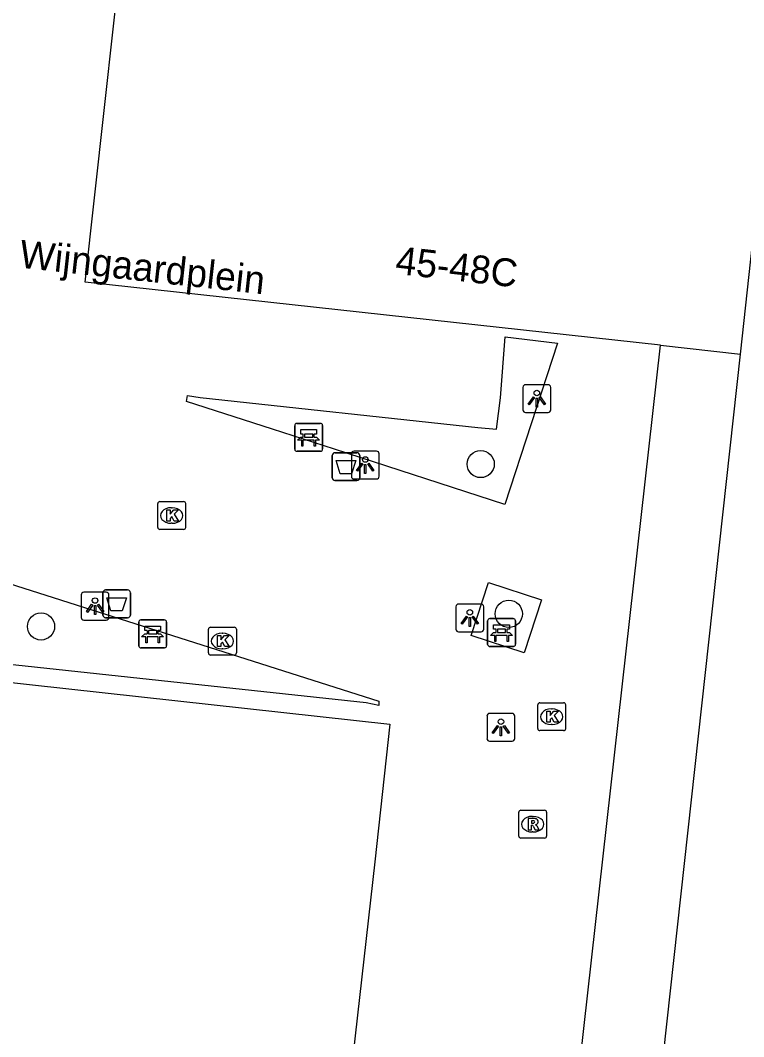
# Model space of a CAD drawing. Extents: x 162026 to 163499, y 387297 to 388169.
# Drawn here: x 162360.5 to 162386.47, y 387569.33 to 387605.84 of the extents above; entities that cross this region are included whole.
import ezdxf

# ---------------------------------------------------------------- set-up
doc = ezdxf.new("R2010")
doc.units = 0
for name, color, linetype in [('IMGEO_Afvalbak', 7, 'Continuous'), ('IMGEO_Bank', 7, 'Continuous'), ('IMGEO_Boom', 7, 'Continuous'), ('IMGEO_Kolk', 7, 'Continuous'), ('IMGEO_Lichtpunt', 7, 'Continuous'), ('IMGEO_Openbare_ruimte_label', 7, 'Continuous'), ('IMGEO_Pand', 7, 'Continuous'), ('IMGEO_Pand_nummerreeks', 7, 'Continuous'), ('IMGEO_Rioolput', 7, 'Continuous'), ('IMGEO_Voetpad_open', 7, 'Continuous')]:
    doc.layers.add(name, color=color, linetype=linetype)

msp = doc.modelspace()

# ---------------------------------------------------------------- linework, layer by layer
at = {"layer": 'IMGEO_Afvalbak'}
for p, q in [((162371.695, 387589.41), (162371.695, 387590.21)), ((162371.695, 387590.21), (162371.695, 387589.41)), ((162371.795, 387590.31), (162372.585, 387590.31)), ((162372.585, 387590.31), (162371.795, 387590.31)), ((162372.685, 387590.21), (162372.685, 387589.41)), ((162372.685, 387589.41), (162372.685, 387590.21)), ((162372.585, 387589.31), (162371.795, 387589.31)), ((162371.795, 387589.31), (162372.585, 387589.31)), ((162363.461, 387584.479), (162363.461, 387585.279)), ((162363.461, 387585.279), (162363.461, 387584.479)), ((162363.561, 387585.379), (162364.351, 387585.379)), ((162364.351, 387585.379), (162363.561, 387585.379)), ((162364.451, 387585.279), (162364.451, 387584.479)), ((162364.451, 387584.479), (162364.451, 387585.279)), ((162364.351, 387584.379), (162363.561, 387584.379)), ((162363.561, 387584.379), (162364.351, 387584.379))]:
    msp.add_line(p, q, dxfattribs=at)
for points in [[(162371.838, 387590.024), (162372.542, 387590.024), (162372.393, 387589.554), (162371.987, 387589.554), (162371.838, 387590.024)], [(162363.604, 387585.093), (162364.308, 387585.093), (162364.159, 387584.623), (162363.753, 387584.623), (162363.604, 387585.093)]]:
    msp.add_lwpolyline(points, dxfattribs=at)
for centre, start, end in [((162371.795, 387590.21), 90, 180), ((162371.795, 387590.21), 90, 180), ((162372.585, 387590.21), 0, 90), ((162372.585, 387590.21), 360, 90), ((162371.795, 387589.41), 180, 270), ((162371.795, 387589.41), 180, 270), ((162372.585, 387589.41), 270, 0), ((162372.585, 387589.41), 270, 0), ((162363.561, 387585.279), 90, 180), ((162363.561, 387585.279), 90, 180), ((162364.351, 387585.279), 0, 90), ((162364.351, 387585.279), 360, 90), ((162363.561, 387584.479), 180, 270), ((162363.561, 387584.479), 180, 270), ((162364.351, 387584.479), 270, 0), ((162364.351, 387584.479), 270, 0)]:
    msp.add_arc(centre, 0.1, start, end, dxfattribs=at)
at = {"layer": 'IMGEO_Bank'}
for p, q in [((162370.349, 387590.437), (162370.349, 387591.278)), ((162370.349, 387591.278), (162370.349, 387590.437)), ((162370.424, 387591.362), (162371.265, 387591.362)), ((162371.265, 387591.362), (162370.424, 387591.362)), ((162371.349, 387591.287), (162371.349, 387590.446)), ((162371.349, 387590.446), (162371.349, 387591.287)), ((162370.658, 387590.868), (162370.658, 387590.974)), ((162370.702, 387590.974), (162370.702, 387590.868)), ((162370.99, 387590.98), (162370.708, 387590.98)), ((162370.996, 387590.868), (162370.996, 387590.974)), ((162371.04, 387590.974), (162371.04, 387590.868)), ((162371.046, 387590.76), (162370.653, 387590.76)), ((162370.708, 387590.862), (162370.99, 387590.862)), ((162371.274, 387590.362), (162370.433, 387590.362)), ((162370.433, 387590.362), (162371.274, 387590.362)), ((162377.35, 387584.348), (162378.191, 387584.348)), ((162378.191, 387584.348), (162377.35, 387584.348)), ((162364.749, 387583.375), (162364.749, 387584.216)), ((162364.749, 387584.216), (162364.749, 387583.375)), ((162364.824, 387584.3), (162365.665, 387584.3)), ((162365.665, 387584.3), (162364.824, 387584.3)), ((162365.749, 387584.225), (162365.749, 387583.384)), ((162365.749, 387583.384), (162365.749, 387584.225)), ((162377.275, 387583.423), (162377.275, 387584.264)), ((162377.275, 387584.264), (162377.275, 387583.423)), ((162378.275, 387584.273), (162378.275, 387583.432)), ((162378.275, 387583.432), (162378.275, 387584.273)), ((162365.446, 387583.698), (162365.053, 387583.698)), ((162365.058, 387583.806), (162365.058, 387583.912)), ((162365.102, 387583.912), (162365.102, 387583.806)), ((162365.39, 387583.918), (162365.108, 387583.918)), ((162365.108, 387583.8), (162365.39, 387583.8)), ((162365.396, 387583.806), (162365.396, 387583.912)), ((162365.44, 387583.912), (162365.44, 387583.806)), ((162377.972, 387583.746), (162377.579, 387583.746)), ((162377.584, 387583.854), (162377.584, 387583.96)), ((162377.628, 387583.96), (162377.628, 387583.854)), ((162377.916, 387583.966), (162377.634, 387583.966)), ((162377.634, 387583.848), (162377.916, 387583.848)), ((162377.922, 387583.854), (162377.922, 387583.96)), ((162377.966, 387583.96), (162377.966, 387583.854)), ((162365.674, 387583.3), (162364.833, 387583.3)), ((162364.833, 387583.3), (162365.674, 387583.3)), ((162378.2, 387583.348), (162377.359, 387583.348)), ((162377.359, 387583.348), (162378.2, 387583.348))]:
    msp.add_line(p, q, dxfattribs=at)
for points in [[(162370.652, 387590.98), (162370.566, 387590.98), (162370.566, 387591.141), (162371.129, 387591.141), (162371.129, 387590.98), (162371.046, 387590.98)], [(162370.596, 387590.76), (162370.454, 387590.76), (162370.566, 387590.862), (162370.652, 387590.862)], [(162370.646, 387590.753), (162370.646, 387590.546), (162370.603, 387590.546), (162370.603, 387590.753)], [(162371.046, 387590.862), (162371.129, 387590.862), (162371.241, 387590.76), (162371.102, 387590.76)], [(162371.096, 387590.753), (162371.096, 387590.546), (162371.052, 387590.546), (162371.052, 387590.753)], [(162365.052, 387583.918), (162364.966, 387583.918), (162364.966, 387584.079), (162365.529, 387584.079), (162365.529, 387583.918), (162365.446, 387583.918)], [(162377.578, 387583.966), (162377.492, 387583.966), (162377.492, 387584.127), (162378.055, 387584.127), (162378.055, 387583.966), (162377.972, 387583.966)], [(162364.996, 387583.698), (162364.854, 387583.698), (162364.966, 387583.8), (162365.052, 387583.8)], [(162365.046, 387583.691), (162365.046, 387583.484), (162365.003, 387583.484), (162365.003, 387583.691)], [(162365.446, 387583.8), (162365.529, 387583.8), (162365.641, 387583.698), (162365.502, 387583.698)], [(162365.496, 387583.691), (162365.496, 387583.484), (162365.452, 387583.484), (162365.452, 387583.691)], [(162377.522, 387583.746), (162377.38, 387583.746), (162377.492, 387583.848), (162377.578, 387583.848)], [(162377.572, 387583.739), (162377.572, 387583.532), (162377.529, 387583.532), (162377.529, 387583.739)], [(162377.972, 387583.848), (162378.055, 387583.848), (162378.167, 387583.746), (162378.028, 387583.746)], [(162378.022, 387583.739), (162378.022, 387583.532), (162377.978, 387583.532), (162377.978, 387583.739)]]:
    msp.add_lwpolyline(points, dxfattribs=at)
for centre, radius, start, end in [((162370.427, 387591.284), 0.0779, 92.4484, 184.2845), ((162370.427, 387591.284), 0.0779, 92.4484, 184.2845), ((162371.271, 387591.284), 0.0779, 2.4484, 94.2845), ((162371.271, 387591.284), 0.0779, 2.4484, 94.2845), ((162370.651, 387590.973), 0.00671, 2.8957, 87.1043), ((162370.708, 387590.973), 0.00671, 92.8957, 177.1043), ((162370.99, 387590.973), 0.00671, 2.8957, 87.1043), ((162371.047, 387590.973), 0.00671, 92.8957, 177.1043), ((162370.596, 387590.753), 0.00671, 2.8957, 87.1043), ((162370.653, 387590.753), 0.00671, 92.8957, 177.1043), ((162370.651, 387590.869), 0.00671, 272.8957, 357.1043), ((162370.708, 387590.869), 0.00671, 182.8957, 267.1043), ((162370.99, 387590.869), 0.00671, 272.8957, 357.1043), ((162371.047, 387590.869), 0.00671, 182.8957, 267.1043), ((162371.045, 387590.753), 0.00671, 2.8957, 87.1043), ((162371.102, 387590.753), 0.00671, 92.8957, 177.1043), ((162370.427, 387590.44), 0.0779, 182.4484, 274.2845), ((162370.427, 387590.44), 0.0779, 182.4484, 274.2845), ((162371.271, 387590.44), 0.0779, 272.4484, 4.2845), ((162371.271, 387590.44), 0.0779, 272.4484, 4.2845), ((162377.353, 387584.27), 0.0779, 92.4484, 184.2845), ((162377.353, 387584.27), 0.0779, 92.4484, 184.2845), ((162378.197, 387584.27), 0.0779, 2.4484, 94.2845), ((162378.197, 387584.27), 0.0779, 2.4484, 94.2845), ((162364.827, 387584.222), 0.0779, 92.4484, 184.2845), ((162364.827, 387584.222), 0.0779, 92.4484, 184.2845), ((162365.671, 387584.222), 0.0779, 2.4484, 94.2845), ((162365.671, 387584.222), 0.0779, 2.4484, 94.2845), ((162364.996, 387583.691), 0.00671, 2.8957, 87.1043), ((162365.053, 387583.691), 0.00671, 92.8957, 177.1043), ((162365.051, 387583.911), 0.00671, 2.8957, 87.1043), ((162365.051, 387583.807), 0.00671, 272.8957, 357.1043), ((162365.108, 387583.911), 0.00671, 92.8957, 177.1043), ((162365.108, 387583.807), 0.00671, 182.8957, 267.1043), ((162365.39, 387583.911), 0.00671, 2.8957, 87.1043), ((162365.39, 387583.807), 0.00671, 272.8957, 357.1043), ((162365.447, 387583.911), 0.00671, 92.8957, 177.1043), ((162365.447, 387583.807), 0.00671, 182.8957, 267.1043), ((162365.445, 387583.691), 0.00671, 2.8957, 87.1043), ((162365.502, 387583.691), 0.00671, 92.8957, 177.1043), ((162377.522, 387583.739), 0.00671, 2.8957, 87.1043), ((162377.579, 387583.739), 0.00671, 92.8957, 177.1043), ((162377.577, 387583.959), 0.00671, 2.8957, 87.1043), ((162377.577, 387583.855), 0.00671, 272.8957, 357.1043), ((162377.634, 387583.959), 0.00671, 92.8957, 177.1043), ((162377.634, 387583.855), 0.00671, 182.8957, 267.1043), ((162377.916, 387583.959), 0.00671, 2.8957, 87.1043), ((162377.916, 387583.855), 0.00671, 272.8957, 357.1043), ((162377.973, 387583.959), 0.00671, 92.8957, 177.1043), ((162377.973, 387583.855), 0.00671, 182.8957, 267.1043), ((162377.971, 387583.739), 0.00671, 2.8957, 87.1043), ((162378.028, 387583.739), 0.00671, 92.8957, 177.1043), ((162364.827, 387583.378), 0.0779, 182.4484, 274.2845), ((162364.827, 387583.378), 0.0779, 182.4484, 274.2845), ((162365.671, 387583.378), 0.0779, 272.4484, 4.2845), ((162365.671, 387583.378), 0.0779, 272.4484, 4.2845), ((162377.353, 387583.426), 0.0779, 182.4484, 274.2845), ((162377.353, 387583.426), 0.0779, 182.4484, 274.2845), ((162378.197, 387583.426), 0.0779, 272.4484, 4.2845), ((162378.197, 387583.426), 0.0779, 272.4484, 4.2845)]:
    msp.add_arc(centre, radius, start, end, dxfattribs=at)
at = {"layer": 'IMGEO_Boom'}
for centre in [(162377.026, 387589.902), (162378.034, 387584.52), (162361.241, 387584.068)]:
    msp.add_circle(centre, 0.489, dxfattribs=at)
at = {"layer": 'IMGEO_Kolk'}
for p, q in [((162365.433, 387587.627), (162365.433, 387588.479)), ((162365.508, 387588.553), (162366.36, 387588.553)), ((162366.434, 387588.479), (162366.434, 387587.627)), ((162365.921, 387588.333), (162365.946, 387588.333)), ((162365.944, 387587.773), (162365.919, 387587.773)), ((162366.36, 387587.553), (162365.508, 387587.553)), ((162367.328, 387584.042), (162368.18, 387584.042)), ((162367.253, 387583.116), (162367.253, 387583.968)), ((162367.741, 387583.822), (162367.766, 387583.822)), ((162368.254, 387583.968), (162368.254, 387583.116)), ((162367.764, 387583.262), (162367.739, 387583.262)), ((162368.18, 387583.042), (162367.328, 387583.042)), ((162379.076, 387580.399), (162379.076, 387581.251)), ((162379.151, 387581.325), (162380.003, 387581.325)), ((162379.564, 387581.105), (162379.589, 387581.105)), ((162380.077, 387581.251), (162380.077, 387580.399)), ((162380.003, 387580.325), (162379.151, 387580.325)), ((162379.587, 387580.545), (162379.562, 387580.545))]:
    msp.add_line(p, q, dxfattribs=at)
for points in [[(162365.433, 387587.627), (162365.433, 387588.479)], [(162365.508, 387588.553), (162366.36, 387588.553)], [(162366.434, 387588.479), (162366.434, 387587.627)], [(162365.754, 387588.253), (162365.877, 387588.253), (162365.877, 387588.102), (162366.007, 387588.253), (162366.171, 387588.253), (162366.025, 387588.102), (162366.178, 387587.853), (162366.026, 387587.853), (162365.941, 387588.017), (162365.877, 387587.95), (162365.877, 387587.853), (162365.754, 387587.853), (162365.754, 387588.253)], [(162366.36, 387587.553), (162365.508, 387587.553)], [(162367.328, 387584.042), (162368.18, 387584.042)], [(162367.253, 387583.116), (162367.253, 387583.968)], [(162367.574, 387583.742), (162367.697, 387583.742), (162367.697, 387583.591), (162367.827, 387583.742), (162367.991, 387583.742), (162367.845, 387583.591), (162367.998, 387583.342), (162367.846, 387583.342), (162367.761, 387583.506), (162367.697, 387583.439), (162367.697, 387583.342), (162367.574, 387583.342), (162367.574, 387583.742)], [(162368.254, 387583.968), (162368.254, 387583.116)], [(162368.18, 387583.042), (162367.328, 387583.042)], [(162379.076, 387580.399), (162379.076, 387581.251)], [(162379.151, 387581.325), (162380.003, 387581.325)], [(162380.077, 387581.251), (162380.077, 387580.399)], [(162379.397, 387581.025), (162379.52, 387581.025), (162379.52, 387580.874), (162379.65, 387581.025), (162379.814, 387581.025), (162379.668, 387580.874), (162379.821, 387580.625), (162379.669, 387580.625), (162379.584, 387580.789), (162379.52, 387580.722), (162379.52, 387580.625), (162379.397, 387580.625), (162379.397, 387581.025)], [(162380.003, 387580.325), (162379.151, 387580.325)]]:
    msp.add_lwpolyline(points, dxfattribs=at)
for centre, start, end in [((162365.51, 387588.477), 91.552, 178.448), ((162365.51, 387588.477), 91.552, 178.448), ((162366.358, 387588.477), 1.552, 88.448), ((162366.358, 387588.477), 1.552, 88.448), ((162365.51, 387587.629), 181.552, 268.448), ((162365.51, 387587.629), 181.552, 268.448), ((162366.358, 387587.629), 271.552, 358.448), ((162366.358, 387587.629), 271.552, 358.448), ((162367.33, 387583.966), 91.552, 178.448), ((162367.33, 387583.966), 91.552, 178.448), ((162368.178, 387583.966), 1.552, 88.448), ((162368.178, 387583.966), 1.552, 88.448), ((162367.33, 387583.118), 181.552, 268.448), ((162367.33, 387583.118), 181.552, 268.448), ((162368.178, 387583.118), 271.552, 358.448), ((162368.178, 387583.118), 271.552, 358.448), ((162379.153, 387581.249), 91.552, 178.448), ((162379.153, 387581.249), 91.552, 178.448), ((162380.001, 387581.249), 1.552, 88.448), ((162380.001, 387581.249), 1.552, 88.448), ((162379.153, 387580.401), 181.552, 268.448), ((162379.153, 387580.401), 181.552, 268.448), ((162380.001, 387580.401), 271.552, 358.448), ((162380.001, 387580.401), 271.552, 358.448)]:
    msp.add_arc(centre, 0.0765, start, end, dxfattribs=at)
for centre, major_axis, ratio, start_param, end_param in [((162365.92, 387588.053), (-0.387, 0.002), 0.722429, 4.712389, 7.853982), ((162365.945, 387588.053), (-0.39, 0.002), 0.717154, 1.570796, 4.712389), ((162367.74, 387583.542), (-0.387, 0.002), 0.722429, 4.712389, 7.853982), ((162367.765, 387583.542), (-0.39, 0.002), 0.717154, 1.570796, 4.712389), ((162379.563, 387580.825), (-0.387, 0.002), 0.722429, 4.712389, 7.853982), ((162379.588, 387580.825), (-0.39, 0.002), 0.717154, 1.570796, 4.712389)]:
    msp.add_ellipse(centre, major_axis=major_axis, ratio=ratio, start_param=start_param, end_param=end_param, dxfattribs=at)
at = {"layer": 'IMGEO_Lichtpunt'}
for p, q in [((162379.446, 387592.752), (162378.638, 387592.752)), ((162379.446, 387592.752), (162378.638, 387592.752)), ((162378.544, 387592.657), (162378.544, 387591.85)), ((162378.544, 387592.657), (162378.544, 387591.85)), ((162379.54, 387591.85), (162379.54, 387592.657)), ((162379.54, 387591.85), (162379.54, 387592.657)), ((162378.638, 387591.756), (162379.446, 387591.756)), ((162378.638, 387591.756), (162379.446, 387591.756)), ((162372.384, 387590.268), (162372.384, 387589.461)), ((162372.384, 387590.268), (162372.384, 387589.461)), ((162373.286, 387590.363), (162372.478, 387590.363)), ((162373.286, 387590.363), (162372.478, 387590.363)), ((162373.38, 387589.461), (162373.38, 387590.268)), ((162373.38, 387589.461), (162373.38, 387590.268)), ((162372.478, 387589.367), (162373.286, 387589.367)), ((162372.478, 387589.367), (162373.286, 387589.367)), ((162362.683, 387585.2), (162362.683, 387584.393)), ((162362.683, 387585.2), (162362.683, 387584.393)), ((162363.585, 387585.295), (162362.777, 387585.295)), ((162363.585, 387585.295), (162362.777, 387585.295)), ((162363.679, 387584.393), (162363.679, 387585.2)), ((162363.679, 387584.393), (162363.679, 387585.2)), ((162376.138, 387584.778), (162376.138, 387583.971)), ((162376.138, 387584.778), (162376.138, 387583.971)), ((162377.04, 387584.873), (162376.232, 387584.873)), ((162377.04, 387584.873), (162376.232, 387584.873)), ((162377.134, 387583.971), (162377.134, 387584.778)), ((162377.134, 387583.971), (162377.134, 387584.778)), ((162362.777, 387584.299), (162363.585, 387584.299)), ((162362.777, 387584.299), (162363.585, 387584.299)), ((162376.232, 387583.877), (162377.04, 387583.877)), ((162376.232, 387583.877), (162377.04, 387583.877)), ((162377.253, 387580.849), (162377.253, 387580.042)), ((162377.253, 387580.849), (162377.253, 387580.042)), ((162378.155, 387580.944), (162377.347, 387580.944)), ((162378.155, 387580.944), (162377.347, 387580.944)), ((162378.249, 387580.042), (162378.249, 387580.849)), ((162378.249, 387580.042), (162378.249, 387580.849)), ((162377.347, 387579.948), (162378.155, 387579.948)), ((162377.347, 387579.948), (162378.155, 387579.948))]:
    msp.add_line(p, q, dxfattribs=at)
for points in [[(162378.918, 387592.321), (162378.957, 387592.293), (162378.769, 387592.031), (162378.731, 387592.058), (162378.918, 387592.321)], [(162379.02, 387592.273), (162379.067, 387592.273), (162379.067, 387591.951), (162379.02, 387591.951), (162379.02, 387592.273)], [(162379.13, 387592.293), (162379.168, 387592.32), (162379.355, 387592.058), (162379.316, 387592.03), (162379.13, 387592.293)], [(162372.758, 387589.932), (162372.797, 387589.904), (162372.609, 387589.642), (162372.571, 387589.669), (162372.758, 387589.932)], [(162372.86, 387589.884), (162372.907, 387589.884), (162372.907, 387589.562), (162372.86, 387589.562), (162372.86, 387589.884)], [(162372.97, 387589.904), (162373.008, 387589.931), (162373.195, 387589.669), (162373.156, 387589.641), (162372.97, 387589.904)], [(162363.057, 387584.864), (162363.096, 387584.836), (162362.908, 387584.574), (162362.87, 387584.601), (162363.057, 387584.864)], [(162363.159, 387584.816), (162363.206, 387584.816), (162363.206, 387584.494), (162363.159, 387584.494), (162363.159, 387584.816)], [(162363.269, 387584.836), (162363.307, 387584.863), (162363.494, 387584.601), (162363.455, 387584.573), (162363.269, 387584.836)], [(162376.512, 387584.442), (162376.551, 387584.414), (162376.363, 387584.152), (162376.325, 387584.179), (162376.512, 387584.442)], [(162376.614, 387584.394), (162376.661, 387584.394), (162376.661, 387584.072), (162376.614, 387584.072), (162376.614, 387584.394)], [(162376.724, 387584.414), (162376.762, 387584.441), (162376.949, 387584.179), (162376.91, 387584.151), (162376.724, 387584.414)], [(162377.627, 387580.513), (162377.666, 387580.485), (162377.478, 387580.223), (162377.44, 387580.25), (162377.627, 387580.513)], [(162377.729, 387580.465), (162377.776, 387580.465), (162377.776, 387580.143), (162377.729, 387580.143), (162377.729, 387580.465)], [(162377.839, 387580.485), (162377.877, 387580.512), (162378.064, 387580.25), (162378.025, 387580.222), (162377.839, 387580.485)]]:
    msp.add_lwpolyline(points, dxfattribs=at)
for centre in [(162379.043, 387592.455), (162372.883, 387590.066), (162363.182, 387584.998), (162376.637, 387584.576), (162377.752, 387580.647)]:
    msp.add_circle(centre, 0.0994, dxfattribs=at)
for centre, start, end in [((162378.638, 387592.657), 90, 180), ((162378.638, 387592.657), 90, 180), ((162379.446, 387592.657), 0, 90), ((162379.446, 387592.657), 0, 90), ((162378.638, 387591.85), 180, 270), ((162378.638, 387591.85), 180, 270), ((162379.446, 387591.85), 270, 0), ((162379.446, 387591.85), 270, 360), ((162372.478, 387590.268), 90, 180), ((162372.478, 387590.268), 90, 180), ((162373.286, 387590.268), 0, 90), ((162373.286, 387590.268), 0, 90), ((162372.478, 387589.461), 180, 270), ((162372.478, 387589.461), 180, 270), ((162373.286, 387589.461), 270, 0), ((162373.286, 387589.461), 270, 360), ((162362.777, 387585.2), 90, 180), ((162362.777, 387585.2), 90, 180), ((162363.585, 387585.2), 0, 90), ((162363.585, 387585.2), 0, 90), ((162376.232, 387584.778), 90, 180), ((162376.232, 387584.778), 90, 180), ((162377.04, 387584.778), 0, 90), ((162377.04, 387584.778), 0, 90), ((162362.777, 387584.393), 180, 270), ((162362.777, 387584.393), 180, 270), ((162363.585, 387584.393), 270, 0), ((162363.585, 387584.393), 270, 360), ((162376.232, 387583.971), 180, 270), ((162376.232, 387583.971), 180, 270), ((162377.04, 387583.971), 270, 0), ((162377.04, 387583.971), 270, 360), ((162377.347, 387580.849), 90, 180), ((162377.347, 387580.849), 90, 180), ((162378.155, 387580.849), 0, 90), ((162378.155, 387580.849), 0, 90), ((162377.347, 387580.042), 180, 270), ((162377.347, 387580.042), 180, 270), ((162378.155, 387580.042), 270, 0), ((162378.155, 387580.042), 270, 360)]:
    msp.add_arc(centre, 0.0946, start, end, dxfattribs=at)
at = {"layer": 'IMGEO_Pand'}
for points in [[(162383.487, 387594.169), (162362.831, 387596.441), (162364.534, 387611.918), (162365.431, 387620.069)], [(162386.349, 387593.854), (162387.447, 387603.869), (162407.859, 387601.627), (162407.825, 387601.316), (162407.369, 387597.19)], [(162383.089, 387564.112), (162386.349, 387593.854)], [(162383.487, 387594.169), (162386.349, 387593.854)], [(162351.943, 387582.961), (162352.454, 387582.905), (162360.935, 387581.973), (162373.768, 387580.561), (162373.225, 387575.616), (162370.078, 387547.752)]]:
    msp.add_lwpolyline(points, dxfattribs=at)
at = {"layer": 'IMGEO_Rioolput'}
for p, q in [((162378.468, 387577.465), (162379.32, 387577.465)), ((162378.393, 387576.539), (162378.393, 387577.391)), ((162378.881, 387577.245), (162378.906, 387577.245)), ((162379.394, 387577.391), (162379.394, 387576.539)), ((162378.904, 387576.685), (162378.879, 387576.685)), ((162379.32, 387576.465), (162378.468, 387576.465))]:
    msp.add_line(p, q, dxfattribs=at)
for points in [[(162378.468, 387577.465), (162379.32, 387577.465)], [(162378.393, 387576.539), (162378.393, 387577.391)], [(162378.982, 387577.163), (162378.73, 387577.165), (162378.73, 387576.765)], [(162378.908, 387577.084), (162378.854, 387577.084), (162378.854, 387577.003)], [(162379.394, 387577.391), (162379.394, 387576.539)], [(162378.73, 387576.765), (162378.854, 387576.765), (162378.854, 387576.927), (162378.865, 387576.927)], [(162378.854, 387577.003), (162378.906, 387577.003)], [(162378.912, 387576.898), (162378.983, 387576.765), (162379.123, 387576.765), (162379.058, 387576.891)], [(162379.32, 387576.465), (162378.468, 387576.465)]]:
    msp.add_lwpolyline(points, dxfattribs=at)
for centre, radius, start, end in [((162378.47, 387577.389), 0.0765, 91.552, 178.448), ((162378.47, 387577.389), 0.0765, 91.552, 178.448), ((162379.318, 387577.389), 0.0765, 1.552, 88.448), ((162379.318, 387577.389), 0.0765, 1.552, 88.448), ((162378.914, 387576.988), 0.0964, 77.0061, 93.1865), ((162378.928, 387577.045), 0.0378, 276.6634, 79.6772), ((162378.981, 387577.053), 0.109, 350.3612, 89.416), ((162378.864, 387576.874), 0.0533, 26.0293, 88.6989), ((162378.89, 387577.192), 0.19, 274.7715, 282.9687), ((162378.979, 387577.053), 0.112, 277.5842, 350.9817), ((162378.963, 387576.838), 0.108, 29.5134, 73.7905), ((162378.47, 387576.541), 0.0765, 181.552, 268.448), ((162378.47, 387576.541), 0.0765, 181.552, 268.448), ((162379.318, 387576.541), 0.0765, 271.552, 358.448), ((162379.318, 387576.541), 0.0765, 271.552, 358.448)]:
    msp.add_arc(centre, radius, start, end, dxfattribs=at)
for centre, major_axis, ratio, start_param, end_param in [((162378.88, 387576.965), (-0.387, 0.002), 0.722429, 4.712389, 7.853982), ((162378.905, 387576.965), (-0.39, 0.002), 0.717154, 1.570796, 4.712389)]:
    msp.add_ellipse(centre, major_axis=major_axis, ratio=ratio, start_param=start_param, end_param=end_param, dxfattribs=at)
at = {"layer": 'IMGEO_Voetpad_open'}
for points in [[(162379.786, 387594.25), (162377.899, 387588.449), (162371.779, 387590.44), (162369.557, 387591.156), (162366.467, 387592.152), (162366.502, 387592.368), (162366.953, 387592.298), (162376.927, 387591.209), (162377.591, 387591.152), (162377.743, 387592.285), (162377.908, 387594.474), (162379.786, 387594.25)], [(162370.078, 387547.752), (162369.725, 387544.71), (162370.028, 387544.676), (162377.504, 387543.833), (162377.835, 387543.796), (162383.487, 387594.169)], [(162373.364, 387581.378), (162373.369, 387581.225), (162372.913, 387581.325), (162359.213, 387582.796), (162360.093, 387585.614), (162371.264, 387582.06), (162373.364, 387581.378)], [(162377.303, 387585.646), (162379.204, 387585.027), (162378.586, 387583.125), (162376.684, 387583.744), (162377.303, 387585.646)]]:
    msp.add_lwpolyline(points, dxfattribs=at)

# ---------------------------------------------------------------- texts
at = {"layer": 'IMGEO_Openbare_ruimte_label'}
msp.add_text('Wijngaardplein', height=1, rotation=353.7421, dxfattribs=at).set_placement((162360.43, 387596.963))
at = {"layer": 'IMGEO_Pand_nummerreeks'}
msp.add_text('45-48C', height=1, rotation=353.5256, dxfattribs=at).set_placement((162373.934, 387596.739))

doc.saveas('drawing.dxf')
